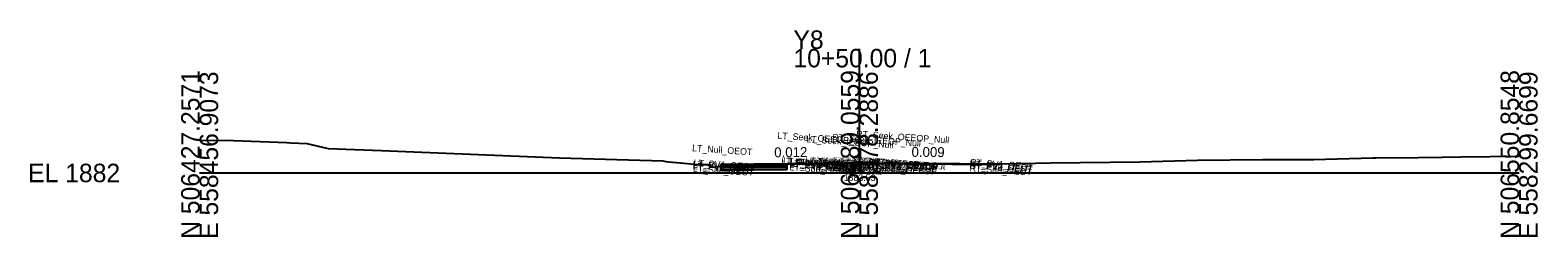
# Model space of a CAD drawing. Extents: x -26 to 203, y -10 to 8070.
# Drawn here: x -25.7 to 202.8, y 490.3 to 521.7 of the extents above; entities that cross this region are included whole.
import ezdxf

# ---------------------------------------------------------------- set-up
doc = ezdxf.new("R2010")
doc.units = 0
for name, color, linetype in [('Default', 7, 'Continuous'), ('Exist Cross Section Cell', 7, 'Continuous'), ('Exist XS Center Line Elevation Label', 7, 'Continuous'), ('Exist XS Ground Line', 7, 'Continuous'), ('Prop CMT Pvmt Course 1', 7, 'Continuous'), ('Prop CMT Pvmt Course 2', 7, 'Continuous'), ('Prop CMT Pvmt Course 3', 7, 'Continuous'), ('Prop CMT Pvmt Surface', 7, 'Continuous'), ('Prop CMT Subgrade Earthwork', 7, 'Continuous'), ('Prop XS Earthwork Shape', 7, 'Continuous'), ('Prop XS SE Text', 7, 'Continuous'), ('Typical Text Grade Point CELL', 7, 'Continuous')]:
    doc.layers.add(name, color=color, linetype=linetype)

msp = doc.modelspace()

# ---------------------------------------------------------------- linework, layer by layer
at = {"layer": 'Exist Cross Section Cell'}
for p, q in [((100, 500), (100, 518.82)), ((0, 500), (100, 500)), ((100, 500), (200, 500))]:
    msp.add_line(p, q, dxfattribs=at)
at = {"layer": 'Exist XS Ground Line'}
for p, q in [((0, 504.99), (5.15, 504.93)), ((5.15, 504.93), (13.2, 504.63)), ((13.2, 504.63), (13.83, 504.59)), ((13.83, 504.59), (16.23, 504.45)), ((16.23, 504.45), (19.48, 503.72)), ((19.48, 503.72), (27.57, 503.43)), ((27.57, 503.43), (54.54, 502.3)), ((54.54, 502.3), (70.19, 501.82)), ((70.19, 501.82), (70.67, 501.76)), ((70.67, 501.76), (71.05, 501.71)), ((71.05, 501.71), (72.86, 501.52)), ((72.86, 501.52), (74.95, 501.31)), ((74.95, 501.31), (75.83, 501.3)), ((75.83, 501.3), (77.04, 501.27)), ((77.04, 501.27), (77.34, 501.12)), ((77.34, 501.12), (77.74, 500.9)), ((77.74, 500.9), (79.19, 501.04)), ((79.19, 501.04), (80.21, 501.19)), ((80.21, 501.19), (81.42, 501.23)), ((81.42, 501.23), (86.91, 501.35)), ((86.91, 501.35), (90.93, 501.42)), ((90.93, 501.42), (100, 501.53)), ((100, 501.53), (100.89, 501.54)), ((100.89, 501.54), (109.37, 501.44)), ((109.37, 501.44), (120.68, 501.37)), ((120.68, 501.37), (124.46, 501.43)), ((124.46, 501.43), (128.98, 501.53)), ((128.98, 501.53), (142.49, 501.69)), ((142.49, 501.69), (151.24, 501.94)), ((151.24, 501.94), (161.08, 502.04)), ((161.08, 502.04), (168.88, 502.05)), ((168.88, 502.05), (177.83, 502.29)), ((177.83, 502.29), (178.29, 502.29)), ((178.29, 502.29), (184.72, 502.36)), ((184.72, 502.36), (188.34, 502.38)), ((188.34, 502.38), (191.17, 502.43)), ((191.17, 502.43), (200, 502.56))]:
    msp.add_line(p, q, dxfattribs=at)
at = {"layer": 'Prop CMT Pvmt Course 1'}
for points in [[(100, 501.53), (98, 501.5), (97.99, 501.5), (94.01, 501.45), (94, 501.45), (79, 501.27)], [(79, 501.27), (79, 501.02)], [(79, 501.02), (89, 501.14)], [(100, 501.53), (102, 501.53), (102.01, 501.53), (105.99, 501.48), (106, 501.48), (121, 501.33)]]:
    msp.add_lwpolyline(points, dxfattribs=at)
at = {"layer": 'Prop CMT Pvmt Course 2'}
for points in [[(89, 501.14), (79, 501.02)], [(79, 501.02), (79, 500.77)], [(79, 500.77), (89, 500.89)]]:
    msp.add_lwpolyline(points, dxfattribs=at)
at = {"layer": 'Prop CMT Pvmt Course 3'}
for points in [[(89, 500.89), (79, 500.77)], [(79, 500.77), (79, 500.4)], [(79, 500.4), (89, 500.52)]]:
    msp.add_lwpolyline(points, dxfattribs=at)
at = {"layer": 'Prop CMT Pvmt Surface'}
for points in [[(100, 501.53), (98, 501.5), (97.99, 501.5), (94.01, 501.45), (94, 501.45), (79, 501.27)], [(100, 501.53), (102, 501.53), (102.01, 501.53), (105.99, 501.48), (106, 501.48), (121, 501.33)]]:
    msp.add_lwpolyline(points, dxfattribs=at)
at = {"layer": 'Prop CMT Subgrade Earthwork'}
for points in [[(79, 500.4), (79, 501.02)], [(89, 500.52), (79, 500.4)], [(89, 500.52), (89, 501.38)]]:
    msp.add_lwpolyline(points, dxfattribs=at)
at = {"layer": 'Prop XS Earthwork Shape'}
for points in [[(79, 501.02), (79.19, 501.04), (80.21, 501.19), (81.42, 501.23), (86.91, 501.35), (90.93, 501.42), (94.01, 501.45), (98, 501.5), (100, 501.53), (102, 501.53), (105.99, 501.48), (109.37, 501.44), (121, 501.33), (121, 501.21), (100, 501.4), (89, 501.27), (89, 500.52), (79, 500.4)], [(100, 501.53), (100.89, 501.54), (102, 501.53)], [(109.37, 501.44), (120.68, 501.37), (121, 501.33)]]:
    msp.add_lwpolyline(points, close=True, dxfattribs=at)

# ---------------------------------------------------------------- texts
at = {"layer": 'Default'}
msp.add_text('-', height=0.0001, dxfattribs=at).set_placement((0, 500))
at = {"layer": 'Exist Cross Section Cell'}
for s, p in [('Y8', (90, 518.82)), ('10+50.00 / 1', (90, 516.02)), ('EL 1882', (-26, 498.6))]:
    msp.add_text(s, height=2.8, dxfattribs=at).set_placement(p)
for s, p in [('N 506427.2571', (0, 490)), ('E 558456.9073', (2.8, 490)), ('N 506489.0559', (100, 490)), ('E 558378.2886', (102.8, 490)), ('N 506550.8548', (200, 490)), ('E 558299.6699', (202.8, 490))]:
    msp.add_text(s, height=2.8, rotation=90, dxfattribs=at).set_placement(p)
at = {"layer": 'Exist XS Center Line Elevation Label'}
msp.add_text('1883.53', height=1, dxfattribs=at).set_placement((97.61, 498.78))
at = {"layer": 'Prop XS SE Text'}
for s, rotation, p in [('0.012', 0.6906, (87.1, 502.37)), ('0.009', 359.4716, (107.9, 502.45))]:
    msp.add_text(s, height=1.5, rotation=rotation, dxfattribs=at).set_placement(p)
at = {"layer": 'Typical Text Grade Point CELL'}
for s, p in [('LT_Seek_OEEOP_Null', (87.55, 505.2)), ('LT_Seek_IEEOP_Null', (91.93, 504.67)), ('RT_Seek_IEEOP_Null', (95.87, 504.93)), ('RT_Seek_OEEOP_Null', (99.49, 505.45)), ('LT_Null_OEOT', (74.62, 503.31)), ('LT_PV2_OEOT', (74.72, 500.82)), ('LT_PV3_OEOT', (74.72, 500.57)), ('LT_Sub_OEOT', (74.74, 500.19)), ('LT_PV1_OEOT', (74.84, 501.06)), ('LT_PV_Sub_Tie_Out', (88.14, 501.36)), ('LT_Null OEEOP Test', (88.4, 501.39)), ('LT_PV2_OEEOP', (89.37, 501.03)), ('LT_PV3_OEEOP', (89.37, 500.78)), ('LT_Sub_OEEOP', (89.39, 500.4)), ('LT_PV1_OEEOP', (89.49, 501.14)), ('LT_Pvmt Out', (90.25, 501.22)), ('LT_Null IEEOP Test', (91.78, 501.4)), ('LT_PV_Sub_Tie_In', (92.76, 501.37)), ('LT_PV2_IEEOP', (93.75, 501.05)), ('LT_PV3_IEEOP', (93.75, 500.8)), ('LT_Sub_IEEOP', (93.77, 500.42)), ('LT_PV1_IEEOP', (93.87, 501.17)), ('Null RT Pvmt Slope', (94.26, 501.45)), ('Null LT Pvmt Slope', (94.32, 501.42)), ('PV1_Overlay_Null', (94.75, 501.27)), ('LT_Pvmt In', (94.84, 501.22)), ('RT_PV_Sub_Tie_In', (96.7, 501.39)), ('RT_Null IEEOP Test', (96.72, 501.42)), ('Sub_PGL', (97.34, 500.34)), ('PV2_PGL', (97.32, 500.96)), ('PV3_PGL', (97.32, 500.71)), ('PV1_PGL', (97.44, 501.2)), ('RT_PV2_IEEOP', (97.69, 501.06)), ('RT_PV3_IEEOP', (97.69, 500.81)), ('RT_Sub_IEEOP', (97.71, 500.43)), ('RT_PV1_IEEOP', (97.81, 501.18)), ('RT_Pvmt In', (98.8, 501.25)), ('CL', (99.2, 501.06)), ('RT_Null OEEOP Test', (99.34, 501.42)), ('RT_PV_Sub_Tie_Out', (100.09, 501.4)), ('RT_PV2_OEEOP', (101.31, 501.05)), ('RT_PV3_OEEOP', (101.31, 500.8)), ('RT_Sub_OEEOP', (101.33, 500.42)), ('RT_PV1_OEEOP', (101.43, 501.16)), ('RT_Pvmt Out', (102.17, 501.25)), ('RT_PV2_OEOT', (116.66, 500.89)), ('RT_PV3_OEOT', (116.66, 500.64)), ('RT_Sub_OEOT', (116.69, 500.26)), ('RT_PV1_OEOT', (116.78, 501.13))]:
    msp.add_text(s, height=1, rotation=356, dxfattribs=at).set_placement(p)

doc.saveas('drawing.dxf')
